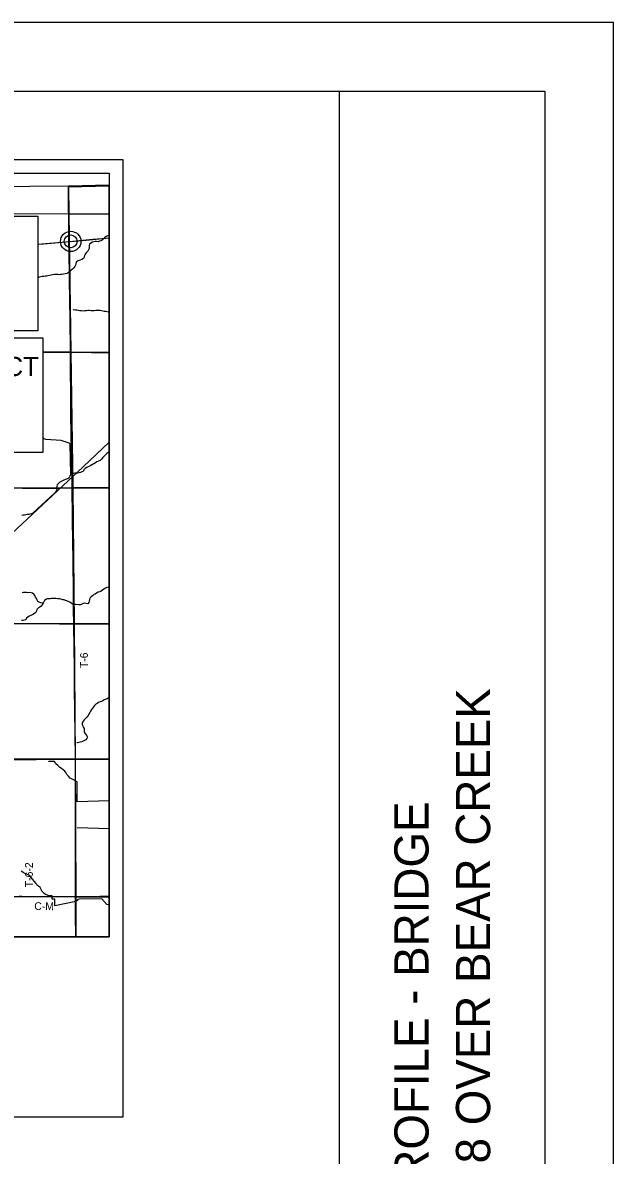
# Model space of a CAD drawing. Extents: x 0 to 34, y 0 to 22.
# Drawn here: x 29.68 to 34, y 13.72 to 22 of the extents above; entities that cross this region are included whole.
import ezdxf

# ---------------------------------------------------------------- set-up
doc = ezdxf.new("R2010")
doc.units = 0
for name, color, linetype in [('GM_X_County', 7, 'Continuous'), ('GM_X_County_Road', 7, 'Continuous'), ('GM_X_County_Road_Text', 7, 'Continuous'), ('GM_X_Minor_River', 7, 'Continuous'), ('GM_X_Rail_Line', 7, 'Continuous'), ('GM_X_Section', 7, 'Continuous'), ('GM_X_State_Route', 7, 'Continuous'), ('GM_X_Township_Road', 7, 'Continuous'), ('GM_X_Township_Road_Text', 7, 'Continuous'), ('GM_X_Township_Text', 7, 'Continuous'), ('GM_X_Unincorporated', 7, 'Continuous'), ('GM_X_Unincorporated_Location', 7, 'Continuous'), ('GM_X_US_Route', 7, 'Continuous'), ('SC_Scratch1', 7, 'Continuous'), ('SH_Border', 7, 'Continuous'), ('SH_Cut_Line', 7, 'Continuous'), ('SH_Data', 7, 'Continuous'), ('SH_Text', 7, 'Continuous')]:
    doc.layers.add(name, color=color, linetype=linetype)

msp = doc.modelspace()

# ---------------------------------------------------------------- linework, layer by layer
at = {"layer": 'GM_X_County'}
msp.add_lwpolyline([(30.3167, 20.8109), (30.0181, 20.8047), (28.8862, 20.7941)], dxfattribs=at)
at = {"layer": 'GM_X_County_Road'}
for points in [[(29.8322, 19.5921), (30.004, 19.5908), (30.0341, 19.5905)], [(30.0341, 19.5905), (30.1874, 19.5887), (30.3167, 19.5874)], [(28.9028, 18.5988), (28.9129, 18.5988), (28.9378, 18.599), (29.3452, 18.5987), (29.5317, 18.5988), (29.6841, 18.5981), (29.9546, 18.5979), (30.0457, 18.5989)], [(30.0457, 18.5989), (30.0603, 18.599), (30.3167, 18.6008)], [(28.9238, 16.608), (28.9258, 16.6086), (28.9279, 16.6091), (28.9301, 16.6094), (28.9321, 16.6096), (28.9337, 16.6096), (28.9467, 16.6099), (28.9871, 16.6102), (29.0835, 16.611), (29.2421, 16.6126), (29.3136, 16.6131), (29.4069, 16.6137), (29.4939, 16.6141), (29.5686, 16.6147), (29.7054, 16.6149), (29.7956, 16.6154), (29.8484, 16.6158), (29.9075, 16.616), (30.0319, 16.6162), (30.0694, 16.6162)], [(30.0694, 16.6162), (30.1905, 16.6164), (30.3167, 16.6167)], [(29.6591, 15.6142), (29.6607, 15.6141), (29.679, 15.6136), (29.7471, 15.6123), (29.8186, 15.6118), (29.8746, 15.6113), (29.9243, 15.6114), (30.0114, 15.6107), (30.0611, 15.6111), (30.0703, 15.6113)], [(30.0703, 15.6113), (30.1108, 15.6121), (30.1481, 15.613), (30.2476, 15.6141), (30.285, 15.6142), (30.3129, 15.6139), (30.3167, 15.6139)]]:
    msp.add_lwpolyline(points, dxfattribs=at)
at = {"layer": 'GM_X_Minor_River'}
msp.add_line((30.3167, 16.1078), (30.083, 16.1152), dxfattribs=at)
for points in [[(30.3167, 20.4452), (30.3133, 20.4446), (30.3038, 20.4413), (30.2943, 20.4376), (30.2836, 20.4297), (30.2751, 20.4196), (30.2644, 20.4102), (30.2549, 20.4054), (30.2454, 20.4021), (30.2354, 20.398), (30.2226, 20.3993), (30.2127, 20.4001), (30.2032, 20.3968), (30.1933, 20.3947), (30.1826, 20.3876), (30.1731, 20.3805), (30.1711, 20.3706), (30.1709, 20.3611), (30.1689, 20.3498), (30.165, 20.3392), (30.1603, 20.329), (30.1492, 20.3177), (30.1407, 20.3068), (30.1364, 20.297), (30.134, 20.2864), (30.1282, 20.2766), (30.1163, 20.2684), (30.1049, 20.2647), (30.0947, 20.2622), (30.0847, 20.257), (30.0748, 20.2484), (30.0728, 20.2381), (30.0703, 20.2279), (30.0649, 20.2174), (30.0568, 20.2076), (30.0484, 20.1978), (30.0384, 20.1903), (30.0281, 20.1809), (30.017, 20.1723), (30.0071, 20.1671), (29.9945, 20.1631), (29.9831, 20.1613), (29.9706, 20.1588), (29.9611, 20.1578), (29.9508, 20.1575), (29.941, 20.1587), (29.9289, 20.1585), (29.9175, 20.1586), (29.9054, 20.1568), (29.8917, 20.1547), (29.8814, 20.1525), (29.8689, 20.1492), (29.859, 20.1471), (29.8491, 20.1464), (29.8389, 20.1454), (29.8268, 20.1432), (29.8165, 20.1418), (29.8062, 20.1393), (29.7961, 20.1353)], [(30.3167, 19.8848), (30.3021, 19.8871), (30.2915, 19.8876), (30.2806, 19.8889), (30.2707, 19.8901), (30.2598, 19.8933), (30.2496, 19.896), (30.2394, 19.8969), (30.2291, 19.8966), (30.2193, 19.8956), (30.2071, 19.8946), (30.1946, 19.8943), (30.1851, 19.8941), (30.1719, 19.8953), (30.1605, 19.8951), (30.1495, 19.894), (30.1378, 19.8934), (30.1279, 19.8916), (30.1146, 19.8937), (30.1021, 19.8934), (30.0912, 19.895), (30.0795, 19.8978), (30.0696, 19.8987), (30.056, 19.9015), (30.053, 19.9042)], [(29.853, 18.9533), (29.8406, 18.9587), (29.8322, 18.9644)], [(30.0352, 18.6975), (30.0314, 18.923), (29.9651, 18.946), (29.853, 18.9533)], [(30.3167, 18.8644), (30.3085, 18.8578), (30.2989, 18.8511), (30.2893, 18.8417), (30.2794, 18.8308), (30.2709, 18.8207), (30.2598, 18.809), (30.2498, 18.8), (30.2384, 18.7933), (30.2266, 18.7889), (30.2166, 18.7814), (30.204, 18.7758), (30.1941, 18.7695), (30.1823, 18.7624), (30.1728, 18.7572), (30.1617, 18.7524), (30.1522, 18.7483), (30.1411, 18.7404), (30.1311, 18.7303), (30.1268, 18.7201), (30.1173, 18.7153), (30.1078, 18.7116), (30.0979, 18.7086), (30.0865, 18.7076), (30.0759, 18.7077), (30.0653, 18.7063), (30.0546, 18.7038), (30.0451, 18.702), (30.0352, 18.6975), (30.0298, 18.6874), (30.0263, 18.6768), (30.0159, 18.6681), (29.9962, 18.6608), (29.9855, 18.6563), (29.9744, 18.6511), (29.9649, 18.6459), (29.955, 18.6403), (29.945, 18.6317), (29.9373, 18.6212), (29.9338, 18.6106), (29.9314, 18.5996), (29.9328, 18.5882), (29.93, 18.578), (29.9238, 18.5667), (29.9196, 18.5625)], [(29.9196, 18.5625), (29.7594, 18.4136)], [(29.7594, 18.4136), (29.7491, 18.4084), (29.7377, 18.407), (29.7282, 18.4044), (29.7172, 18.4034), (29.7073, 18.402), (29.6979, 18.4002), (29.6876, 18.3992), (29.677, 18.3981)], [(29.8343, 17.7553), (29.826, 17.7573), (29.8158, 17.7597), (29.8053, 17.7632), (29.7955, 17.7686), (29.7903, 17.7793), (29.7844, 17.79), (29.7773, 17.8011), (29.7733, 17.8117), (29.7654, 17.8217), (29.7557, 17.8297), (29.7459, 17.8329), (29.7341, 17.8334), (29.7239, 17.8331), (29.7125, 17.8332), (29.7012, 17.8333), (29.6913, 17.8334), (29.6811, 17.8313)], [(30.3167, 17.8757), (30.3106, 17.8744), (30.2999, 17.8703), (30.2904, 17.8655), (30.2782, 17.858), (30.2678, 17.8513), (30.2575, 17.8435), (30.2472, 17.8383), (30.237, 17.8357), (30.2244, 17.8286), (30.2148, 17.8215), (30.2053, 17.8193), (30.195, 17.8096), (30.1854, 17.8017), (30.1751, 17.7931), (30.1715, 17.7825), (30.1706, 17.7708), (30.1686, 17.7605), (30.1598, 17.7508), (30.148, 17.7528), (30.1371, 17.7556), (30.1272, 17.7538), (30.1165, 17.7486), (30.1063, 17.7453)], [(30.1063, 17.7453), (30.0949, 17.745), (30.0737, 17.7467), (30.0616, 17.7472), (30.0495, 17.7485), (30.039, 17.7566), (30.0292, 17.7635), (30.0168, 17.769), (30.0058, 17.7725), (29.996, 17.7771), (29.9862, 17.7807), (29.9767, 17.78), (29.9639, 17.7858), (29.9526, 17.7871), (29.9416, 17.7891), (29.9276, 17.7904), (29.9166, 17.7905), (29.906, 17.7898), (29.8946, 17.7903), (29.884, 17.7882), (29.8734, 17.7879), (29.8639, 17.7873), (29.8536, 17.7843), (29.8441, 17.7761), (29.8386, 17.7655), (29.8343, 17.7553), (29.827, 17.7451), (29.8197, 17.7354), (29.8097, 17.7279), (29.8002, 17.7227), (29.7902, 17.7129), (29.7859, 17.7023), (29.782, 17.6925), (29.7736, 17.6824), (29.764, 17.676), (29.7537, 17.6719), (29.7431, 17.6671), (29.7328, 17.6615), (29.7228, 17.6548), (29.7132, 17.6462), (29.707, 17.6352), (29.6968, 17.6319), (29.6858, 17.6305), (29.6755, 17.6299)], [(30.3167, 17.0649), (30.3099, 17.0615), (30.3004, 17.0578), (30.2805, 17.0489), (30.2702, 17.0437), (30.2603, 17.0385), (30.2501, 17.0351), (30.2394, 17.0303), (30.2287, 17.024), (30.2184, 17.0177), (30.2088, 17.0083), (30.1934, 16.9887), (30.1876, 16.9781), (30.181, 16.9676), (30.174, 16.957), (30.1675, 16.9457), (30.1624, 16.9344), (30.1528, 16.9235), (30.1428, 16.9134), (30.1324, 16.9032), (30.1262, 16.8927), (30.1193, 16.8814), (30.1195, 16.8707), (30.1228, 16.8605), (30.1268, 16.8509), (30.1324, 16.8395), (30.1334, 16.8289), (30.1336, 16.8179), (30.1388, 16.8068), (30.1455, 16.7973), (30.1526, 16.7866), (30.1577, 16.7763), (30.1527, 16.7665), (30.1457, 16.7567), (30.1259, 16.747), (30.1153, 16.743), (30.1042, 16.7393), (30.094, 16.7379), (30.0837, 16.7361), (30.0803, 16.735)], [(30.3167, 16.3109), (30.0824, 16.3041), (30.082, 16.4505), (30.0511, 16.4679), (30.0323, 16.4775), (30.0181, 16.4929), (30.0076, 16.5047), (30.0006, 16.5177), (29.992, 16.5292), (29.9676, 16.5476), (29.9568, 16.5557), (29.9406, 16.5692), (29.9275, 16.5814), (29.9205, 16.5921), (29.916, 16.5979), (29.8762, 16.5983), (29.8736, 16.6017)], [(30.3167, 15.5512), (30.3161, 15.5517), (30.3002, 15.553), (30.2636, 15.5959), (30.0972, 15.5927), (30.0866, 15.5913), (30.0827, 15.5822), (30.0735, 15.5762), (29.9185, 15.5441), (29.9184, 15.5927), (29.8994, 15.5925), (29.8993, 15.6164), (29.877, 15.6166), (29.8585, 15.624), (29.8521, 15.6279), (29.8424, 15.6352), (29.8278, 15.6486), (29.8192, 15.6627), (29.8118, 15.6791), (29.8002, 15.6872), (29.7915, 15.6919), (29.7878, 15.6968), (29.7823, 15.7064), (29.7327, 15.7687), (29.7187, 15.773), (29.7043, 15.777), (29.6882, 15.7874), (29.6728, 15.7978)]]:
    msp.add_lwpolyline(points, dxfattribs=at)
at = {"layer": 'GM_X_Rail_Line'}
for points in [[(29.7961, 20.3802), (30.1481, 20.4102), (30.3167, 20.4279)], [(27.0345, 15.3175), (27.0356, 15.4259), (27.0494, 15.5562), (27.0656, 15.6449), (27.0886, 15.7152), (27.1197, 15.8028), (27.1531, 15.872), (27.1854, 15.9273), (27.2223, 15.9838), (27.2614, 16.0437), (27.3144, 16.1048), (27.4089, 16.2005), (27.94, 16.6983), (28.7611, 17.4753), (29.4921, 18.1638), (30.1262, 18.7537), (30.3167, 18.9329)]]:
    msp.add_lwpolyline(points, dxfattribs=at)
at = {"layer": 'GM_X_Section'}
for points in [[(30.3167, 20.601), (30.3167, 20.8052), (30.0195, 20.7969), (30.0212, 20.6024)], [(30.3167, 19.5899), (30.3167, 20.601), (30.0212, 20.6024), (30.0362, 19.5914)], [(30.3167, 18.5994), (30.3167, 19.5899), (30.0362, 19.5914), (30.0497, 18.599)], [(28.9028, 18.5982), (30.0497, 18.599), (30.0593, 17.6044), (28.914, 17.6074), (28.9031, 18.5906)], [(30.3167, 17.6051), (30.3167, 18.5994), (30.0497, 18.599), (30.0593, 17.6044)], [(28.914, 17.6074), (30.0593, 17.6044), (30.0675, 16.617), (28.9274, 16.6074), (28.9139, 17.6013)], [(30.3167, 16.6171), (30.3167, 17.6051), (30.0593, 17.6044), (30.0675, 16.617)], [(28.9274, 16.6074), (30.0675, 16.617), (30.0715, 15.6092), (28.9324, 15.6152), (28.9273, 16.6021)], [(30.3167, 15.6103), (30.3167, 16.6171), (30.0675, 16.617), (30.0715, 15.6092)]]:
    msp.add_lwpolyline(points, close=True, dxfattribs=at)
for points in [[(28.8872, 20.5861), (28.8871, 20.5965), (28.8869, 20.6082), (30.0212, 20.6024), (30.0362, 19.5914), (29.8322, 19.5929)], [(29.8322, 19.5929), (30.0362, 19.5914), (30.0497, 18.599), (28.9028, 18.5982), (28.9007, 18.8568)], [(28.9345, 15.3175), (28.9324, 15.6152), (30.0715, 15.6092), (30.0727, 15.3175)], [(30.3167, 15.3175), (30.3167, 15.6103), (30.0715, 15.6092), (30.0727, 15.3175)]]:
    msp.add_lwpolyline(points, dxfattribs=at)
at = {"layer": 'GM_X_State_Route'}
msp.add_lwpolyline([(29.7961, 20.3804), (29.8364, 20.3841), (29.92, 20.3917), (30.0006, 20.3985), (30.0224, 20.4004), (30.0275, 20.4009), (30.1978, 20.4162), (30.2659, 20.4229), (30.3167, 20.4275)], dxfattribs=at)
at = {"layer": 'GM_X_Township_Road'}
for points in [[(30.0224, 20.4004), (30.0212, 20.4393), (30.0205, 20.5792), (30.0201, 20.6445), (30.0183, 20.7719), (30.0183, 20.8041)], [(30.0341, 19.5905), (30.0304, 19.8426), (30.0289, 19.9545), (30.0239, 20.3244), (30.0224, 20.3989), (30.0224, 20.4004)], [(30.0457, 18.5989), (30.0449, 18.6427), (30.0424, 18.795), (30.0415, 18.8727), (30.0391, 18.9971), (30.0372, 19.1276), (30.0363, 19.2364), (30.0346, 19.5162), (30.0342, 19.5877), (30.0341, 19.5905)], [(30.0578, 17.6054), (30.0565, 17.7102), (30.0554, 17.8035), (30.0523, 18.0957), (30.0513, 18.1858), (30.0457, 18.5961), (30.0457, 18.5989)], [(30.0694, 16.6162), (30.0694, 16.6223), (30.0673, 16.8026), (30.0638, 17.1321), (30.0618, 17.2782), (30.0579, 17.5921), (30.0578, 17.6054)], [(30.0703, 15.6113), (30.0702, 15.6183), (30.0703, 15.7737), (30.0702, 15.926), (30.0699, 16.1995), (30.0696, 16.3829), (30.0694, 16.6162)], [(30.0722, 15.3175), (30.0722, 15.323), (30.0712, 15.4722), (30.0703, 15.6113)]]:
    msp.add_lwpolyline(points, dxfattribs=at)
at = {"layer": 'GM_X_Township_Text'}
msp.add_lwpolyline([(30.3167, 15.3175), (30.3167, 16.6173), (30.1903, 16.617), (30.0692, 16.6168), (30.0317, 16.6167), (29.9073, 16.6166), (29.8482, 16.6163), (29.7953, 16.6159), (29.7052, 16.6155), (29.5683, 16.6152)], dxfattribs=at)
at = {"layer": 'GM_X_Unincorporated'}
for radius in [0.0744, 0.0472]:
    msp.add_circle((30.0351, 20.4011), radius, dxfattribs=at)
at = {"layer": 'GM_X_Unincorporated_Location'}
msp.add_line((30.0351, 20.4011), (30.0351, 20.4011), dxfattribs=at)
at = {"layer": 'GM_X_US_Route'}
msp.add_lwpolyline([(29.6225, 17.6086), (29.7312, 17.6076), (29.7685, 17.6073), (29.7995, 17.607), (29.8492, 17.607), (29.8738, 17.6068), (29.8947, 17.6066), (29.9544, 17.6059), (30.0578, 17.6054), (30.1598, 17.605), (30.17, 17.6053), (30.2001, 17.6052), (30.2468, 17.605), (30.309, 17.6049), (30.3167, 17.6049)], dxfattribs=at)
at = {"layer": 'SC_Scratch1'}
msp.add_lwpolyline([(23.5167, 20.6789), (23.5167, 15.3175), (30.3167, 15.3175), (30.3167, 20.8109), (30.0181, 20.8047), (28.8862, 20.7941), (27.8891, 20.7835), (26.8843, 20.7634), (25.88, 20.7414), (25.1253, 20.7174), (23.8668, 20.6853)], close=True, dxfattribs=at)
at = {"layer": 'SH_Border'}
msp.add_line((32, 0.5), (32, 21.5), dxfattribs=at)
msp.add_lwpolyline([(1.5, 21.5), (33.5, 21.5), (33.5, 0.5), (1.5, 0.5)], close=True, dxfattribs=at)
at = {"layer": 'SH_Cut_Line'}
msp.add_lwpolyline([(0, 0), (34, 0), (34, 22), (0, 22)], close=True, dxfattribs=at)
at = {"layer": 'SH_Data'}
for points in [[(23.4167, 21), (30.4167, 21), (30.4167, 14), (23.4167, 14)], [(23.5167, 20.9), (30.3167, 20.9), (30.3167, 15.3175), (23.5167, 15.3175)], [(28.1535, 20.5861), (29.7961, 20.5861), (29.7961, 19.7461), (28.1535, 19.7461)], [(28.1535, 19.6968), (29.8322, 19.6968), (29.8322, 18.8568), (28.1535, 18.8568)]]:
    msp.add_lwpolyline(points, close=True, dxfattribs=at)

# ---------------------------------------------------------------- texts
at = {"layer": 'GM_X_County_Road_Text'}
msp.add_text('C-M', height=0.05682, rotation=359.26784, dxfattribs=at).set_placement((29.7687, 15.5139))
at = {"layer": 'GM_X_Township_Road_Text'}
for s, rotation, p in [('T-6', 90.4772, (30.1613, 17.2818)), ('T-6-2', 90, (29.7588, 15.6801))]:
    msp.add_text(s, height=0.05682, rotation=rotation, dxfattribs=at).set_placement(p)
at = {"layer": 'SH_Data'}
for s, p in [('BRIDGE NO. FUL-109-1698 OVER BEAR CREEK', (33.1, 9.6295)), ('GEOTECHNICAL PROFILE - BRIDGE', (32.65, 10.5665))]:
    msp.add_text(s, height=0.25, rotation=90, dxfattribs=at).set_placement(p)
at = {"layer": 'SH_Text'}
msp.add_text('BEGIN PROJECT', height=0.14, dxfattribs=at).set_placement((28.2935, 19.4168))

doc.saveas('drawing.dxf')
